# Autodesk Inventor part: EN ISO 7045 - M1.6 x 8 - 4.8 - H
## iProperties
Comments: To add or edit properties for Autodesk Inventor files, use iProperties.
Company: ACME-Hardware
Created: 2003-12
Part Number: EN ISO 7045 - M1.6 x 8 - 4.8 - H
Vendor: Autodesk Inc.
Document SubType Name: Modeling
Designer: Administrator
Material: Default
Description: Recessed Pan Head Screw
Standard: EN ISO 7045
Size Designation: M1.6 x 8 - 4.8 - H
Density: 1 g/cm^3
Alert: To add or edit properties for Autodesk Inventor files, use iProperties.
Control State: 0
Master: False
Checked Out: False
Shininess: 64.0
Length Units: 11269
Angle Units: 11279
Time Units: 11290
Mass Units: 11283
Length Display Precision: 3
Angle Display Precision: 2
Compacted: True
EGR: 1
Density: 0.0
Volumn: 0.0
Area: 0.0
PropertySet Name: Model Information
Author: Administrator
Revision Number: 8
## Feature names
1. Body [Revolution]
2. Slot [Extrusion]
3. Cut [Revolution]
4. Fillet1
5. Fillet2
6. Chamfer1
